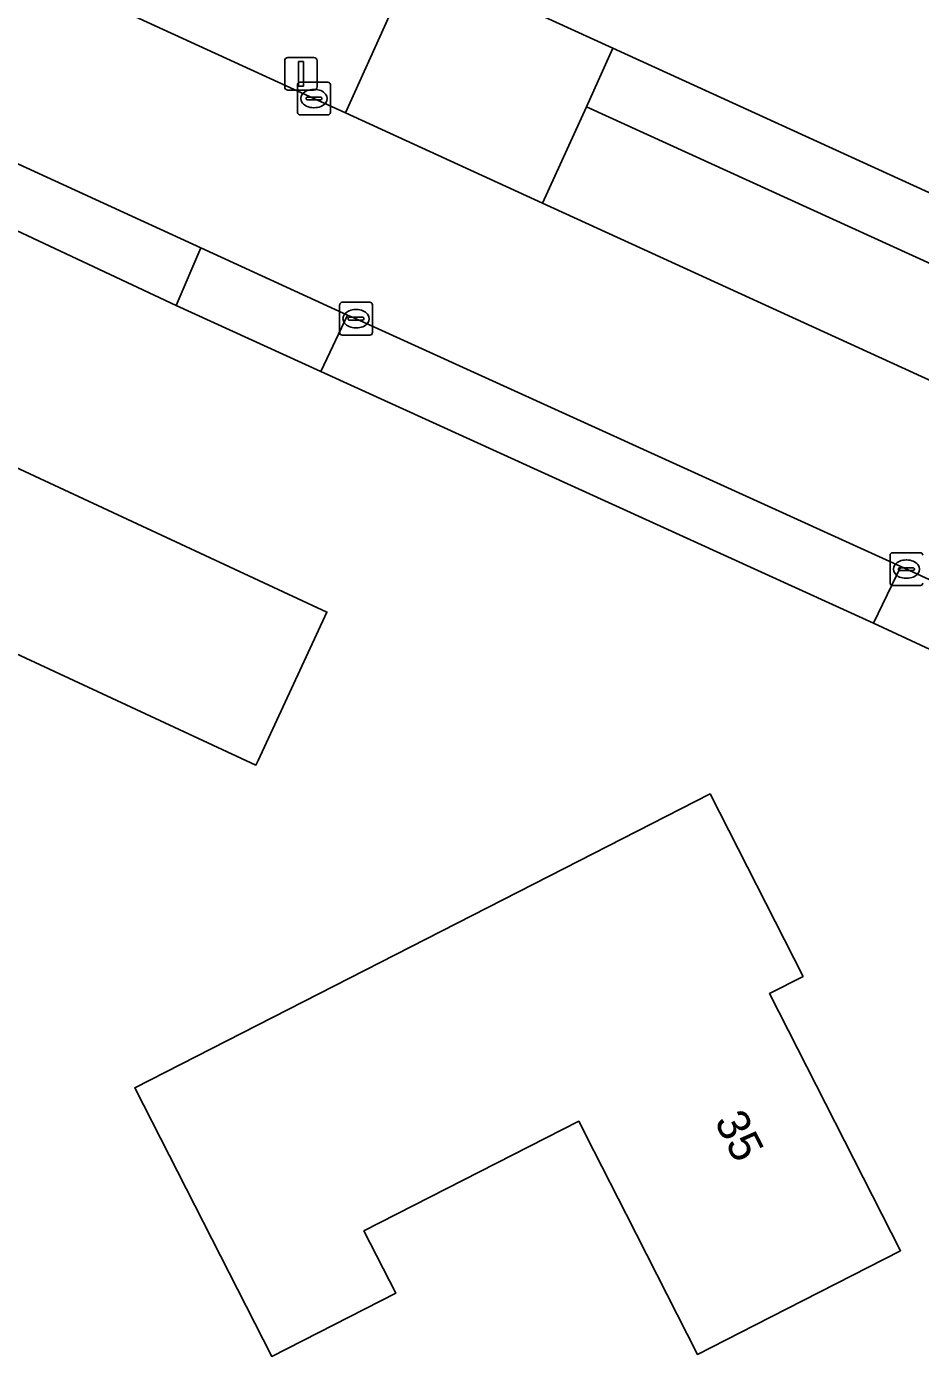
# Model space of a CAD drawing. Extents: x 162722 to 165104, y 384719 to 386284.
# Drawn here: x 164060.76 to 164088.06, y 385121.86 to 385162.47 of the extents above; entities that cross this region are included whole.
import ezdxf

# ---------------------------------------------------------------- set-up
doc = ezdxf.new("R2010")
doc.units = 0
for name, color, linetype in [('IMGEO_Erf', 7, 'Continuous'), ('IMGEO_Groenvoorziening', 7, 'Continuous'), ('IMGEO_Kolk', 7, 'Continuous'), ('IMGEO_Lichtmast', 7, 'Continuous'), ('IMGEO_Pand', 7, 'Continuous'), ('IMGEO_Pand_nummerreeks', 7, 'Continuous'), ('IMGEO_Parkeervlak_open', 7, 'Continuous'), ('IMGEO_Rijbaan_lokaal_gesloten', 7, 'Continuous'), ('IMGEO_Voetpad_open', 7, 'Continuous')]:
    doc.layers.add(name, color=color, linetype=linetype)

msp = doc.modelspace()

# ---------------------------------------------------------------- linework, layer by layer
at = {"layer": 'IMGEO_Erf'}
for points in [[(164036.204, 385181.139), (164039.945, 385179.482), (164072.64, 385164.57), (164078.669, 385161.813), (164095.502, 385154.125), (164099.033, 385152.538), (164099.324, 385152.404), (164101.923, 385153.628), (164120.431, 385163.473), (164142.636, 385174.734), (164131.602, 385206.911)], [(164088.358, 385143.446), (164086.624, 385144.253), (164069.744, 385151.933), (164065.329, 385153.951), (164051.353, 385160.508)]]:
    msp.add_lwpolyline(points, dxfattribs=at)
for points in [[(164049.78, 385139.755), (164045.245, 385141.862), (164048.193, 385148.208), (164046.985, 385148.769), (164049.662, 385154.531), (164060.462, 385149.513), (164060.262, 385149.081), (164069.933, 385144.587), (164067.827, 385140.053), (164067.763, 385139.916), (164057.79, 385144.549), (164054.536, 385137.545)], [(164064.061, 385130.065), (164077.183, 385136.762), (164081.636, 385139.035), (164084.48, 385133.465), (164083.448, 385132.938), (164087.456, 385125.084), (164083.003, 385122.811), (164081.257, 385121.92), (164079.072, 385126.201), (164078.084, 385128.137), (164077.623, 385129.04), (164071.064, 385125.692), (164072.033, 385123.791), (164068.249, 385121.86)]]:
    msp.add_lwpolyline(points, close=True, dxfattribs=at)
at = {"layer": 'IMGEO_Groenvoorziening'}
for points in [[(164071.832, 385162.783), (164052.189, 385171.716), (164050.878, 385168.812), (164053.648, 385167.548), (164069.537, 385160.271), (164070.499, 385159.839)], [(164094.653, 385152.361), (164077.858, 385160.016), (164076.52, 385157.072), (164089.52, 385151.131), (164092.233, 385149.841), (164093.194, 385149.352)]]:
    msp.add_lwpolyline(points, close=True, dxfattribs=at)
at = {"layer": 'IMGEO_Kolk'}
for p, q in [((164069.036, 385159.845), (164069.036, 385160.697)), ((164069.111, 385160.771), (164069.963, 385160.771)), ((164069.524, 385160.551), (164069.549, 385160.551)), ((164070.037, 385160.697), (164070.037, 385159.845)), ((164069.295, 385160.265), (164069.295, 385160.277)), ((164069.733, 385160.228), (164069.335, 385160.228)), ((164069.338, 385160.314), (164069.736, 385160.314)), ((164069.547, 385159.991), (164069.522, 385159.991)), ((164069.779, 385160.277), (164069.779, 385160.265)), ((164069.963, 385159.771), (164069.111, 385159.771)), ((164070.321, 385153.122), (164070.321, 385153.974)), ((164070.396, 385154.048), (164071.248, 385154.048)), ((164071.322, 385153.974), (164071.322, 385153.122)), ((164070.58, 385153.542), (164070.58, 385153.554)), ((164071.018, 385153.505), (164070.62, 385153.505)), ((164070.623, 385153.591), (164071.021, 385153.591)), ((164070.809, 385153.828), (164070.834, 385153.828)), ((164071.064, 385153.554), (164071.064, 385153.542)), ((164070.832, 385153.268), (164070.807, 385153.268)), ((164071.248, 385153.048), (164070.396, 385153.048)), ((164087.135, 385145.475), (164087.135, 385146.327)), ((164087.21, 385146.401), (164088.062, 385146.401)), ((164087.623, 385146.181), (164087.648, 385146.181)), ((164087.394, 385145.895), (164087.394, 385145.907)), ((164087.832, 385145.858), (164087.434, 385145.858)), ((164087.437, 385145.944), (164087.835, 385145.944)), ((164087.878, 385145.907), (164087.878, 385145.895)), ((164088.062, 385145.401), (164087.21, 385145.401)), ((164087.646, 385145.621), (164087.621, 385145.621))]:
    msp.add_line(p, q, dxfattribs=at)
for points in [[(164069.036, 385159.845), (164069.036, 385160.697)], [(164069.111, 385160.771), (164069.963, 385160.771)], [(164070.037, 385160.697), (164070.037, 385159.845)], [(164069.963, 385159.771), (164069.111, 385159.771)], [(164070.321, 385153.122), (164070.321, 385153.974)], [(164070.396, 385154.048), (164071.248, 385154.048)], [(164071.322, 385153.974), (164071.322, 385153.122)], [(164071.248, 385153.048), (164070.396, 385153.048)], [(164087.135, 385145.475), (164087.135, 385146.327)], [(164087.21, 385146.401), (164088.062, 385146.401)], [(164088.062, 385145.401), (164087.21, 385145.401)]]:
    msp.add_lwpolyline(points, dxfattribs=at)
for centre, radius, start, end in [((164069.113, 385160.695), 0.0765, 91.552, 178.448), ((164069.113, 385160.695), 0.0765, 91.552, 178.448), ((164069.961, 385160.695), 0.0765, 1.552, 88.448), ((164069.961, 385160.695), 0.0765, 1.552, 88.448), ((164069.335, 385160.274), 0.0403, 85.8775, 175.7526), ((164069.332, 385160.264), 0.0366, 178.938, 274.7102), ((164069.736, 385160.271), 0.043, 264.8664, 352.4533), ((164069.74, 385160.276), 0.0386, 1.7309, 96.639), ((164069.113, 385159.847), 0.0765, 181.552, 268.448), ((164069.113, 385159.847), 0.0765, 181.552, 268.448), ((164069.961, 385159.847), 0.0765, 271.552, 358.448), ((164069.961, 385159.847), 0.0765, 271.552, 358.448), ((164070.398, 385153.972), 0.0765, 91.552, 178.448), ((164070.398, 385153.972), 0.0765, 91.552, 178.448), ((164071.246, 385153.972), 0.0765, 1.552, 88.448), ((164071.246, 385153.972), 0.0765, 1.552, 88.448), ((164070.62, 385153.551), 0.0403, 85.8775, 175.7526), ((164070.617, 385153.541), 0.0366, 178.938, 274.7102), ((164071.021, 385153.548), 0.043, 264.8664, 352.4533), ((164071.025, 385153.553), 0.0386, 1.7309, 96.639), ((164070.398, 385153.124), 0.0765, 181.552, 268.448), ((164070.398, 385153.124), 0.0765, 181.552, 268.448), ((164071.246, 385153.124), 0.0765, 271.552, 358.448), ((164071.246, 385153.124), 0.0765, 271.552, 358.448), ((164087.212, 385146.325), 0.0765, 91.552, 178.448), ((164087.212, 385146.325), 0.0765, 91.552, 178.448), ((164088.06, 385146.325), 0.0765, 1.552, 88.448), ((164088.06, 385146.325), 0.0765, 1.552, 88.448), ((164087.434, 385145.904), 0.0403, 85.8775, 175.7526), ((164087.431, 385145.894), 0.0366, 178.938, 274.7102), ((164087.835, 385145.901), 0.043, 264.8664, 352.4533), ((164087.839, 385145.906), 0.0386, 1.7309, 96.639), ((164087.212, 385145.477), 0.0765, 181.552, 268.448), ((164087.212, 385145.477), 0.0765, 181.552, 268.448), ((164088.06, 385145.477), 0.0765, 271.552, 358.448), ((164088.06, 385145.477), 0.0765, 271.552, 358.448)]:
    msp.add_arc(centre, radius, start, end, dxfattribs=at)
for centre, major_axis, ratio, start_param, end_param in [((164069.523, 385160.271), (-0.387, 0.002), 0.722429, 4.712389, 7.853982), ((164069.548, 385160.271), (-0.39, 0.002), 0.717154, 1.570796, 4.712389), ((164070.808, 385153.548), (-0.387, 0.002), 0.722429, 4.712389, 7.853982), ((164070.833, 385153.548), (-0.39, 0.002), 0.717154, 1.570796, 4.712389), ((164087.622, 385145.901), (-0.387, 0.002), 0.722429, 4.712389, 7.853982), ((164087.647, 385145.901), (-0.39, 0.002), 0.717154, 1.570796, 4.712389)]:
    msp.add_ellipse(centre, major_axis=major_axis, ratio=ratio, start_param=start_param, end_param=end_param, dxfattribs=at)
at = {"layer": 'IMGEO_Lichtmast'}
for p, q in [((164068.642, 385160.625), (164068.642, 385161.425)), ((164068.642, 385161.425), (164068.642, 385160.625)), ((164068.742, 385161.525), (164069.532, 385161.525)), ((164069.532, 385161.525), (164068.742, 385161.525)), ((164069.632, 385161.425), (164069.632, 385160.625)), ((164069.632, 385160.625), (164069.632, 385161.425)), ((164069.532, 385160.525), (164068.742, 385160.525)), ((164068.742, 385160.525), (164069.532, 385160.525))]:
    msp.add_line(p, q, dxfattribs=at)
msp.add_lwpolyline([(164069.062, 385161.4), (164069.212, 385161.4), (164069.212, 385160.65), (164069.062, 385160.65), (164069.062, 385161.4)], dxfattribs=at)
for centre, start, end in [((164068.742, 385161.425), 90, 180), ((164068.742, 385161.425), 90, 180), ((164069.532, 385161.425), 0, 90), ((164069.532, 385161.425), 360, 90), ((164068.742, 385160.625), 180, 270), ((164068.742, 385160.625), 180, 270), ((164069.532, 385160.625), 270, 0), ((164069.532, 385160.625), 270, 0)]:
    msp.add_arc(centre, 0.1, start, end, dxfattribs=at)
at = {"layer": 'IMGEO_Pand'}
for points in [[(164049.78, 385139.755), (164054.536, 385137.545), (164057.79, 385144.549), (164067.763, 385139.916), (164067.827, 385140.053), (164069.933, 385144.587), (164060.262, 385149.081), (164060.462, 385149.513), (164049.662, 385154.531), (164046.985, 385148.769), (164048.193, 385148.208), (164045.245, 385141.862)], [(164083.448, 385132.938), (164084.48, 385133.465), (164081.636, 385139.035), (164077.183, 385136.762), (164064.061, 385130.065), (164068.249, 385121.86), (164072.033, 385123.791), (164071.064, 385125.692), (164077.623, 385129.04), (164078.084, 385128.137), (164079.072, 385126.201), (164081.257, 385121.92), (164083.003, 385122.811), (164087.456, 385125.084)]]:
    msp.add_lwpolyline(points, close=True, dxfattribs=at)
at = {"layer": 'IMGEO_Parkeervlak_open'}
msp.add_lwpolyline([(164051.353, 385160.508), (164065.329, 385153.951), (164066.085, 385155.714), (164054.177, 385161.165), (164052.042, 385162.153)], dxfattribs=at)
msp.add_lwpolyline([(164070.822, 385153.548), (164070.562, 385153.657), (164069.744, 385151.933), (164086.624, 385144.253), (164087.459, 385145.983)], close=True, dxfattribs=at)
at = {"layer": 'IMGEO_Rijbaan_lokaal_gesloten'}
for points in [[(164093.194, 385149.352), (164092.233, 385149.841), (164089.52, 385151.131), (164076.52, 385157.072), (164070.499, 385159.839), (164069.537, 385160.271), (164053.648, 385167.548)], [(164054.177, 385161.165), (164066.085, 385155.714), (164070.562, 385153.657), (164070.822, 385153.548), (164087.459, 385145.983), (164089.478, 385145.059), (164089.735, 385144.935), (164090.614, 385144.447), (164091.447, 385143.882), (164092.225, 385143.245), (164092.944, 385142.541), (164093.597, 385141.775), (164094.179, 385140.954), (164094.685, 385140.085), (164099.69, 385142.353), (164099.129, 385143.415), (164097.379, 385145.782), (164096.382, 385146.876), (164095.552, 385147.684), (164094.654, 385148.415), (164093.693, 385149.062), (164093.194, 385149.352)]]:
    msp.add_lwpolyline(points, dxfattribs=at)
at = {"layer": 'IMGEO_Voetpad_open'}
for points in [[(164076.52, 385157.072), (164077.858, 385160.016), (164078.669, 385161.813), (164072.64, 385164.57), (164071.832, 385162.783), (164070.499, 385159.839)], [(164094.653, 385152.361), (164095.502, 385154.125), (164078.669, 385161.813), (164077.858, 385160.016)], [(164066.085, 385155.714), (164065.329, 385153.951), (164069.744, 385151.933), (164070.562, 385153.657)]]:
    msp.add_lwpolyline(points, close=True, dxfattribs=at)
msp.add_lwpolyline([(164092.985, 385139.198), (164094.685, 385140.085), (164094.179, 385140.954), (164093.597, 385141.775), (164092.944, 385142.541), (164092.225, 385143.245), (164091.447, 385143.882), (164090.614, 385144.447), (164089.735, 385144.935), (164089.478, 385145.059), (164087.459, 385145.983), (164086.624, 385144.253), (164088.358, 385143.446)], dxfattribs=at)

# ---------------------------------------------------------------- texts
at = {"layer": 'IMGEO_Pand_nummerreeks'}
msp.add_text('35', height=1, rotation=297.0377, dxfattribs=at).set_placement((164081.754, 385129.043))

doc.saveas('drawing.dxf')
